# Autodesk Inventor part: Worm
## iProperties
Created: 2008-01
Part Number: Worm
Material: Steel, Mild
Document SubType Name: Modeling
Designer: eruiz-tagle
Mass: 4.82459 g
Surface Area: 11.9593 cm^2
Volume: 0.613815 cm^3
Density: 7.86 g/cm^3
CustomPartVersion: 1
Author: eruiz-tagle
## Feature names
1. Base Body [Extrusion]
2. Chamfer1
3. Chamfer2
4. Tooth
5. Tooth Pattern [Circular Pattern]
6. Left Tooth
7. Left Tooth Pattern [Circular Pattern]
